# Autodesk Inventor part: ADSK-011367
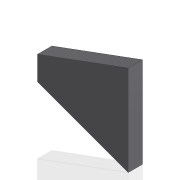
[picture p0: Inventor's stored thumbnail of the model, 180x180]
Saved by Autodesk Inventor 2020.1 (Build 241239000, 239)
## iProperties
Created: 1999-12
Part Number: ADSK-011367
Material: Acier doux
Document SubType Name: Modeling
Designer: sspink
Density: 7.86 g/cm^3
Appearance: Metal-Steel(Polish)
Mass: 43.0099 g
Surface Area: 25.9796 cm^2
Volume: 5.472 cm^3
Control State: 0
Checked Out: False
Master: False
Shininess: 0.0
Length Units: 11269
Angle Units: 11279
Time Units: 11290
Mass Units: 11283
Length Display Precision: 3
Angle Display Precision: 2
Compacted: True
Dimensions: 38x38x6 mm
Mass: 0,043 kg
DocNumber: ADSK-011367.ipt
Folder: 01 - Themengebiete\Simplification\01 - Packaging machine\
VDS_Category: 3D Komponenten
Density: 0.0
Volumn: 0.0
Area: 0.0
PropertySet Name: Model Information
Author: sspink
Revision Number: -
Title: support
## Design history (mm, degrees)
node "Solide1"
  node "Extrusion1" dims "d3" = 6, "d4" = 0
sketch "Sketch1"
  geometry: L1 (6.217, -14.274)-(-31.783, -0.274); L2 (-31.783, -0.274)-(-31.783, 9.726); L3 (-31.783, 9.726)-(6.217, 23.726); L4 (6.217, 23.726)-(6.217, -14.274) reference; L5 (-31.783, 4.726)-(6.217, 4.726) reference
  constraints: 10 end point, 2 midpoint, 2 vertical, 1 equal length, 1 horizontal, 1 parallel
  dimensions: "d0" = 38 distance of L3.end L1.start; "d1" = 10 distance of L1.end L2.end; "d2" = 38 distance between parallel lines of L2 L4
node "Corps solides"
node "Corps surfaciques"
